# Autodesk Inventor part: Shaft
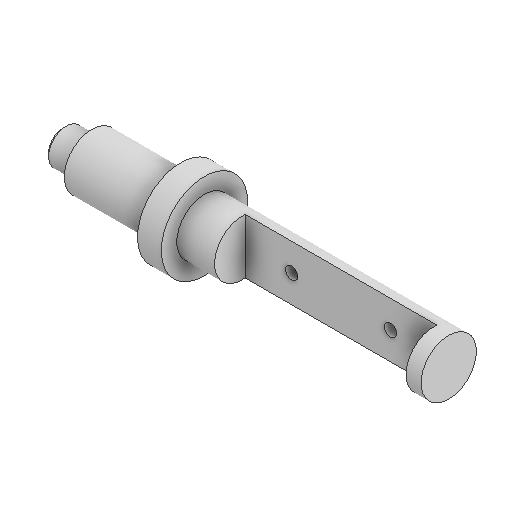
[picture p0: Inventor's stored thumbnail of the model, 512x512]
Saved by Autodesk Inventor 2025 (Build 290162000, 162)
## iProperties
Created: 2019-03
Part Number: Shaft
Material: Generic
Document SubType Name: Modeling
Designer: LENOVO-CADCIM
Density: 1 g/cm^3
Appearance: Default
Author: LENOVO-CADCIM
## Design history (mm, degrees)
sketch "Sketch1"
  geometry: L1 (284.311, 0)-(1023.188, 0); L2 (391.676, 0)-(391.676, -18); L3 (391.676, -18)-(420.576, -18); L4 (420.576, -18)-(420.576, -28); L5 (420.576, -28)-(510.376, -28); L6 (510.376, -28)-(510.376, -43.6); L7 (510.376, -43.6)-(534.376, -43.6); L8 (534.376, -43.6)-(534.376, -28); L9 (534.376, -28)-(781.476, -28); L10 (781.476, -28)-(781.476, 0); L11 (391.676, 0)-(781.476, 0); 1 further point
  constraints: 22 end point, 8 perpendicular, 5 point on line, 1 collinear, 1 horizontal
  dimensions: "d0" = 28.9 distance of L2.end L3.end; "d1" = 89.8 distance of L4.end L5.end; "d2" = 24 distance of L6.end L7.end; "d3" = 247.1 distance of L8.end L9.end; "d4" = 56 diameter of L9 L1; "d5" = 87.2 diameter of L7 L1; "d6" = 36 diameter of L3 L1
revolve "Revolution1" sketch "Sketch1" stored, may be unused: angle "d7" = 90 deg
sketch "Sketch4"
  geometry: L1 (-781.476, 28)-(-534.376, 28) reference; L2 (-572.576, 28)-(-766.376, 28); L3 (-766.376, 28)-(-766.376, -3.1); L4 (-766.376, -3.1)-(-572.576, -3.1); L5 (-572.576, -3.1)-(-572.576, 28); L6 (-781.476, -28)-(-534.376, -28) reference; 2 further points
  constraints: 8 end point, 2 parallel, 1 horizontal, 1 perpendicular, 1 point on line
  dimensions: "d16" = 24.9 distance between parallel lines of L6 L4; "d17" = 15.1 distance from line of L1.start L3; "d40" = 193.8 distance of L3.end L4.end
extrude "Extrusion3" cut sketch "Sketch4" stored distance "d18" = 257; taper "d19" = 0 deg
sketch "Sketch6"
  geometry: L1 (-180.9, 45.828)-(-180.9, 9.828) reference; L2 (-180.9, 27.828)-(320.546, 27.828); L3 (0, 55.828)-(0, -0.172) reference; 5 further points
  constraints: 2 end point, 2 point on line, 1 horizontal, 1 midpoint
  dimensions: "d24" = 100 distance of point (46.9, 27.828) point (146.9, 27.828); "d25" = 46.9 distance from line of L3 point (46.9, 27.828)
hole "Hole1" sketch "Sketch6" at (46.9, 27.828), (146.9, 27.828) diameter "d26" = 12.5; stored, may be unused: countersink angle "d30" = 90 deg, drill point angle "d32" = 118 deg; dims "d27" = 6, "d28" = 100, "d29" = 25, "d31" = 310
chamfer "Chamfer1" distance "d33" = 3; stored, may be unused: second distance "d34" = 2, angle "d35" = 45 deg
sketch "Sketch7"
  geometry: L1 (8, -22)-(-8, -22); L2 (-8, -22)-(-8, -26.833); L3 (8, -26.833)-(8, -22); L4 (0, 0)-(0, 64); C1 r 28 at (0, 0) reference; A1 r 28 centre (0, 0) between (-8, -26.833) and (8, -26.833); A2 r 28 centre (0, 0) between (8, -26.833) and (-8, -26.833) reference; 4 further points
  constraints: 8 end point, 3 point on circle, 1 centre point, 1 coincident, 1 concentric, 1 horizontal, 1 parallel, 1 perpendicular, 1 vertical, 1 other
  dimensions: "d36" = 16 distance between parallel lines of L3 L2; "d37" = 50 distance from line of point (0, 28) L1
extrude "Extrusion5" cut sketch "Sketch7" distance "d38" = 62.5; taper "d39" = 0 deg
body "Solid1"
